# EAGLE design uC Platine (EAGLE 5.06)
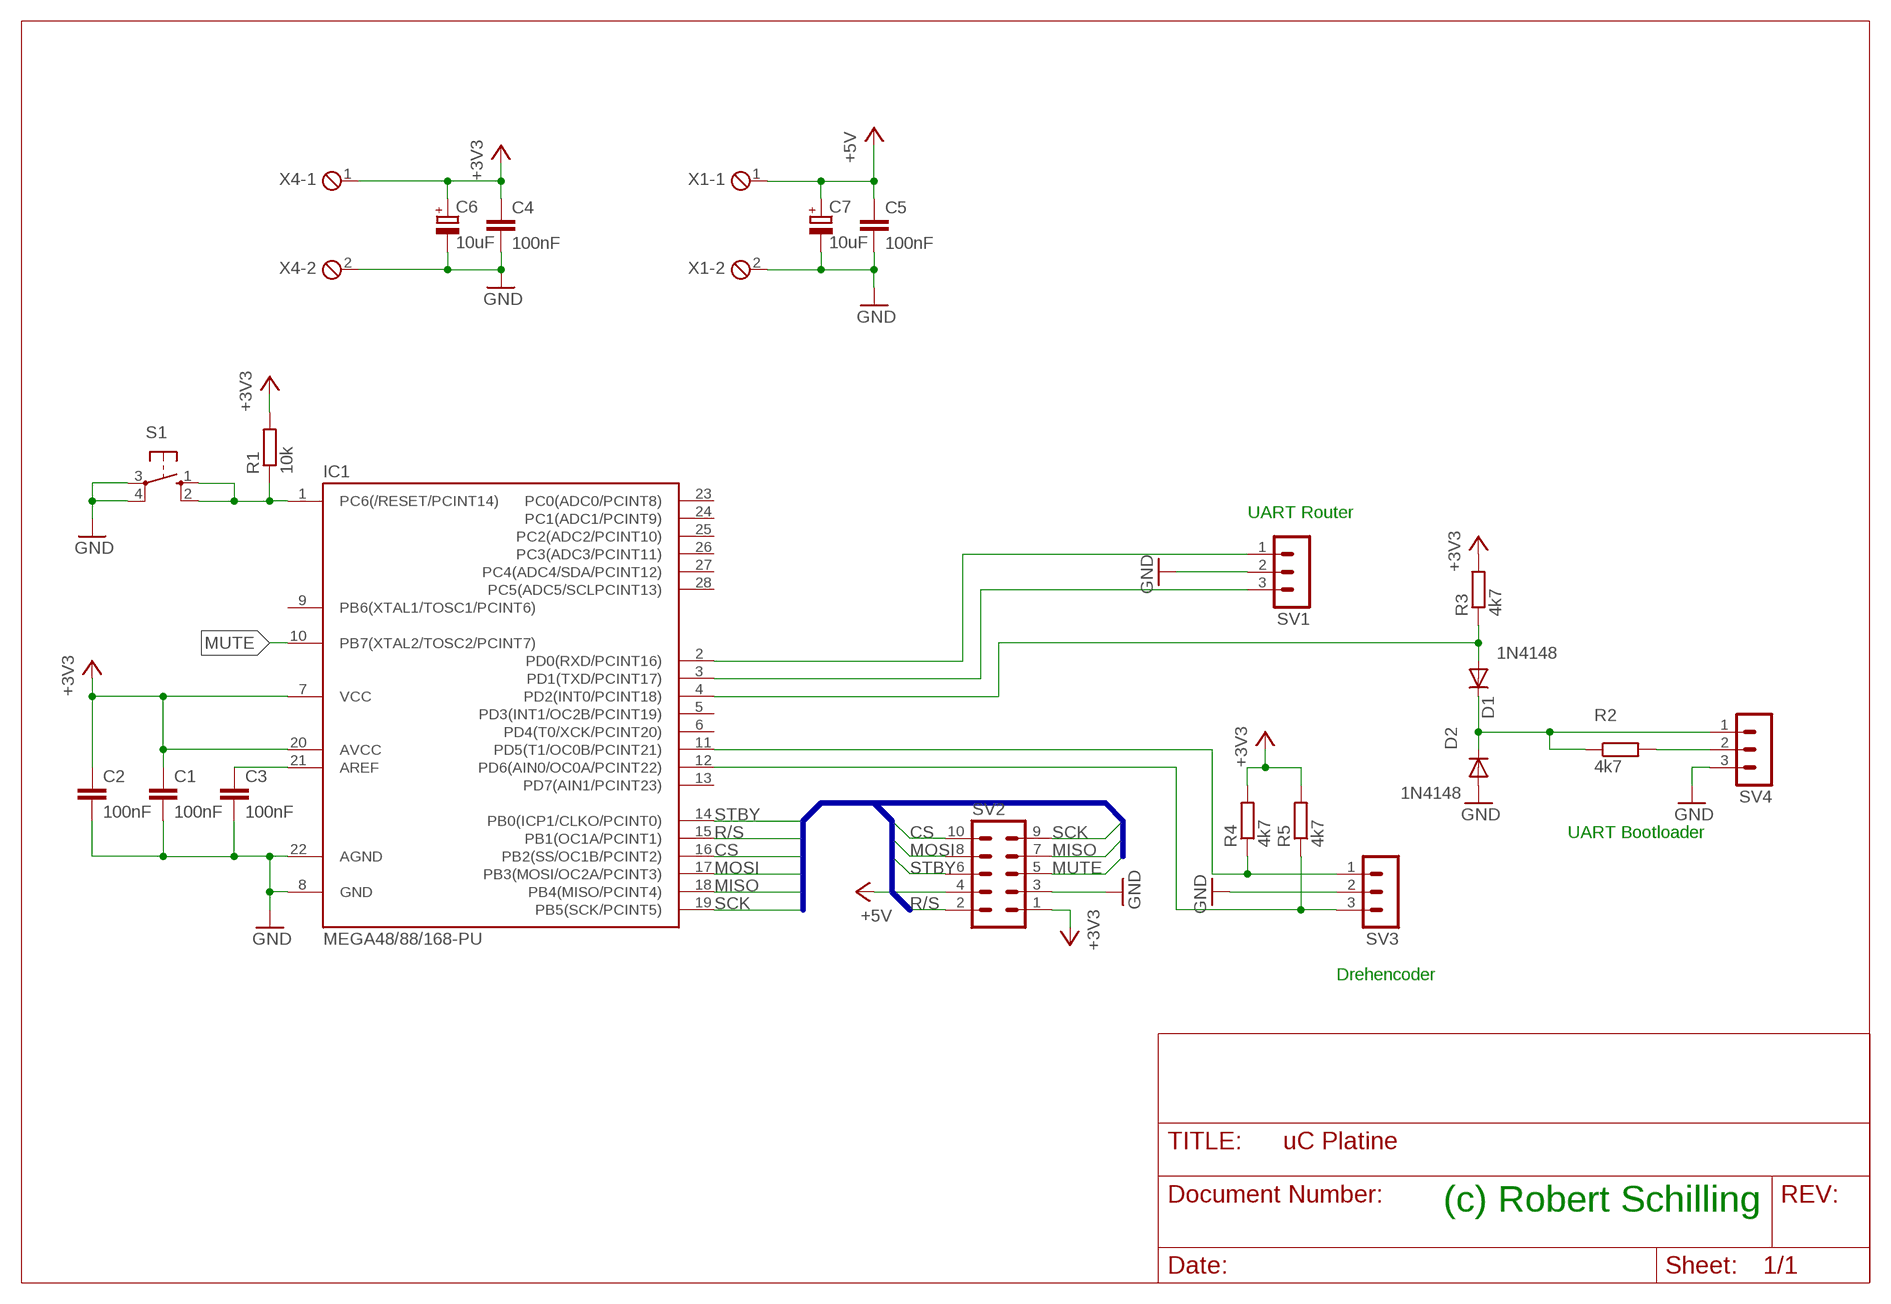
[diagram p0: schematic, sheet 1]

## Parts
C1  100nF  C-EUC0805  [C0805]
C2  100nF  C-EUC0805  [C0805]
C3  100nF  C-EUC0805  [C0805]
C4  100nF  C-EUC0805  [C0805]
C5  100nF  C-EUC0805  [C0805]
C6  10uF  CPOL-EUE2.5-6  [E2,5-6]
C7  10uF  CPOL-EUE2.5-6  [E2,5-6]
D1  1N4148  DIODE-MINIMELF  [MINIMELF]
D2  1N4148  DIODE-MINIMELF  [MINIMELF]
IC1  MEGA48/88/168-PU  [DIL28-3]
R1  10k  R-EU_M0805  [M0805]
R2  4k7  R-EU_M0805  [M0805]
R3  4k7  R-EU_M0805  [M0805]
R4  4k7  R-EU_M0805  [M0805]
R5  4k7  R-EU_M0805  [M0805]
S1  10-XX  [B3F-10XX]
SV1  MA03-1  [MA03-1]
SV2  ML10  [ML10]
SV3  MA03-1  [MA03-1]
SV4  MA03-1  [MA03-1]
X1  MKDS1.5-2  [MKDS1.5-2]
X4  MKDS1.5-2  [MKDS1.5-2]

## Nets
+3V3: C1.1 C2.1 C4.1 C6.+ IC1.7(VCC) IC1.20(AVCC) R1.2 R3.2 R4.2 R5.2 SV2.1 X4.1
+5V: C5.1 C7.+ SV2.4 X1.1
CS: IC1.16(PB2(SS/OC1B/PCINT2)) SV2.10
GND: C1.2 C2.2 C3.2 C4.2 C5.2 C6.- C7.- D2.A IC1.8(GND) IC1.22(AGND) S1.3(P) S1.4(P1) SV1.2 SV2.3 SV3.2 SV4.3 X1.2 X4.2
MISO: IC1.18(PB4(MISO/PCINT4)) SV2.7
MOSI: IC1.17(PB3(MOSI/OC2A/PCINT3)) SV2.8
MUTE: IC1.10(PB7(XTAL2/TOSC2/PCINT7)) SV2.5
N$1: IC1.2(PD0(RXD/PCINT16)) SV1.1
N$2: C3.1 IC1.21(AREF)
N$3: D1.C D2.C R2.1 SV4.1
N$4: R2.2 SV4.2
N$5: IC1.1(PC6(/RESET/PCINT14)) R1.1 S1.1(S) S1.2(S1)
N$6: IC1.3(PD1(TXD/PCINT17)) SV1.3
N$7: D1.A IC1.4(PD2(INT0/PCINT18)) R3.1
N$9: IC1.11(PD5(T1/OC0B/PCINT21)) R4.1 SV3.1
N$10: IC1.12(PD6(AIN0/OC0A/PCINT22)) R5.1 SV3.3
R/S: IC1.15(PB1(OC1A/PCINT1)) SV2.2
SCK: IC1.19(PB5(SCK/PCINT5)) SV2.9
STBY: IC1.14(PB0(ICP1/CLKO/PCINT0)) SV2.6
Unconnected: IC1.5(PD3(INT1/OC2B/PCINT19)) IC1.6(PD4(T0/XCK/PCINT20)) IC1.9(PB6(XTAL1/TOSC1/PCINT6)) IC1.13(PD7(AIN1/PCINT23)) IC1.23(PC0(ADC0/PCINT8)) IC1.24(PC1(ADC1/PCINT9)) IC1.25(PC2(ADC2/PCINT10)) IC1.26(PC3(ADC3/PCINT11)) IC1.27(PC4(ADC4/SDA/PCINT12)) IC1.28(PC5(ADC5/SCLPCINT13))

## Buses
B$1

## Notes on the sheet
- UART Router
- UART Bootloader
- Drehencoder
- (c) Robert Schilling

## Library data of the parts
C1-C5 = resistor:C-EU: CAPACITOR, European symbol
C6 C7 = resistor:CPOL-EU: POLARIZED CAPACITOR, European symbol
D1 D2 = diode:DIODE-: DIODE
IC1 = avr-6:MEGA48/88/168-PU
R1-R5 = rcl:R-EU_: RESISTOR, European symbol
S1 = switch-omron:10-XX: OMRON SWITCH
SV1 SV3 SV4 = con-lstb:MA03-1: PIN HEADER
SV2 = con-harting-ml:ML10: HARTING
X1 X4 = HTL-Diplomarbeit_Knapp:MKDS1.5-2

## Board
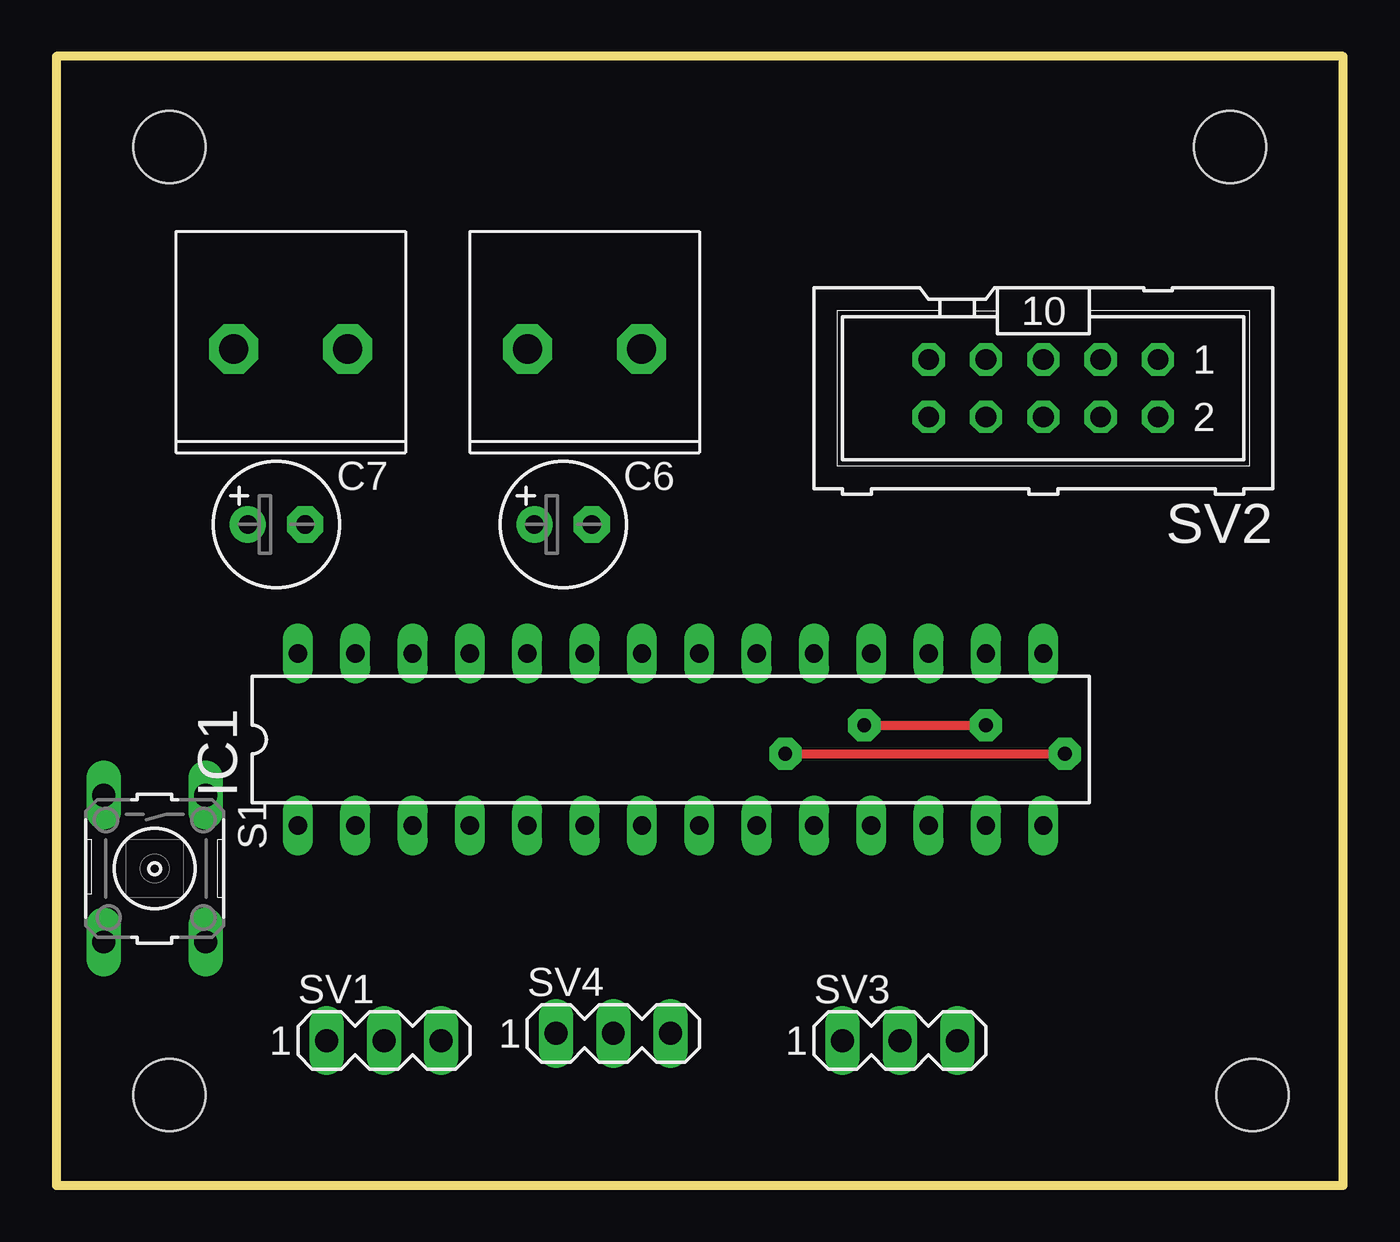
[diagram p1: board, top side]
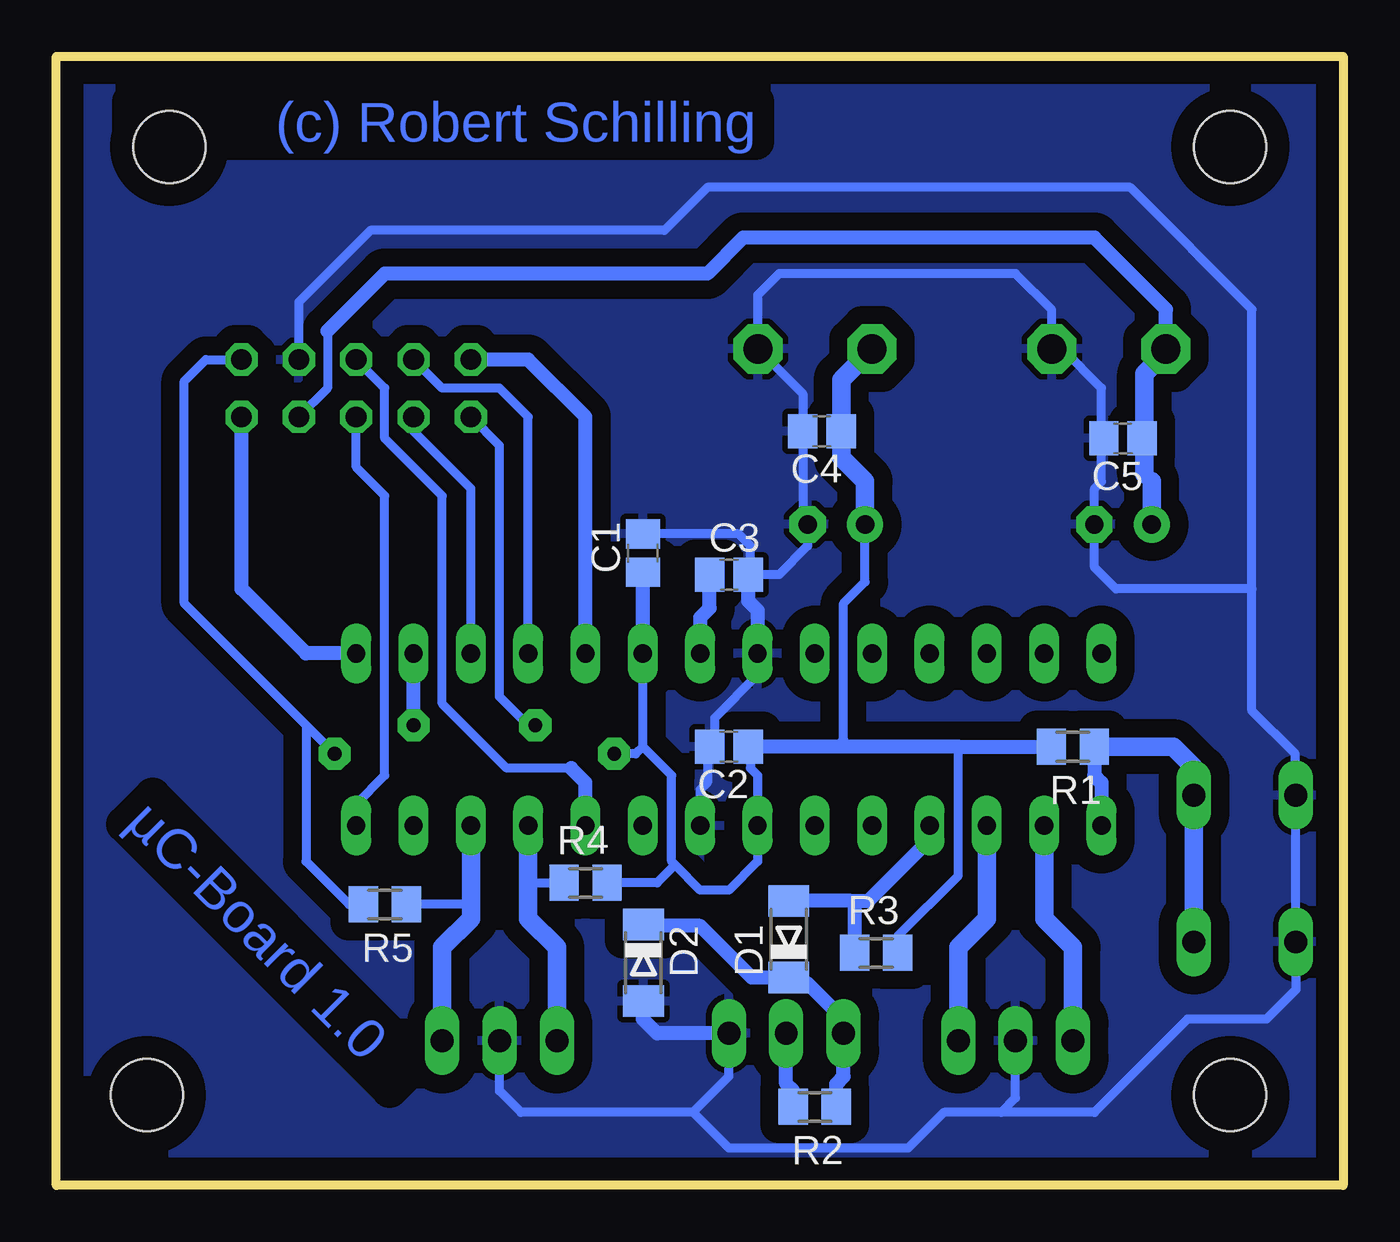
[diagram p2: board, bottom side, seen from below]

Size 57 x 50 mm. Coordinates in mm from the lower left corner, seen from the top.
Outline: 0,0 57,0 57,50 0,50 0,0
Copper layers (1*16): Top 0.035mm / dielectric 1.5mm / Bottom 0.035mm
Design rules "default *": minimum track width 10mil, minimum drill 24mil, track to track 8mil, track to pad 8mil, pad to pad 8mil, via to via 8mil, smd to smd 8mil, copper to edge 40mil, drill to drill 8mil, minimum pad ring 10mil, minimum via ring 8mil, stop-mask expansion 4mil, vias tented up to drill 0mil, thermal gap 10mil
Holes 3.2 mm at 52,46 53,4 5,4 5,46

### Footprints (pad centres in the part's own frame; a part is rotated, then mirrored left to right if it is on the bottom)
C0805 = smd 1.3 x 1.5: 1 -0.85,0; 2 0.85,0
E2,5-6 = drill 0.813 pad 1.6 round: + -1.27,0 | drill 0.813 pad 1.6 octagon: - 1.27,0
MINIMELF = smd 1.4 x 1.8: A 1.7,0; C -1.7,0
DIL28-3 = drill 0.813 long: 1 -16.51,-3.81; 2 -13.97,-3.81; 3 -11.43,-3.81; 4 -8.89,-3.81; 5 -6.35,-3.81; 6 -3.81,-3.81; 7 -1.27,-3.81; 8 1.27,-3.81; 9 3.81,-3.81; 10 6.35,-3.81; 11 8.89,-3.81; 12 11.43,-3.81; 13 13.97,-3.81; 14 16.51,-3.81; 15 16.51,3.81; 16 13.97,3.81; 17 11.43,3.81; 18 8.89,3.81; 19 6.35,3.81; 20 3.81,3.81; 21 1.27,3.81; 22 -1.27,3.81; 23 -3.81,3.81; 24 -6.35,3.81; 25 -8.89,3.81; 26 -11.43,3.81; 27 -13.97,3.81; 28 -16.51,3.81
M0805 = smd 1.3 x 1.6: 1 -0.95,0; 2 0.95,0
B3F-10XX = drill 1.016 long: 1 -3.251,2.261; 2 3.251,2.261; 3 -3.251,-2.261; 4 3.251,-2.261
MA03-1 = drill 1.016 long: 1 -2.54,0; 2 0,0; 3 2.54,0
ML10 = drill 0.914 octagon: 1 -5.08,-1.27; 2 -5.08,1.27; 3 -2.54,-1.27; 4 -2.54,1.27; 5 0,-1.27; 6 0,1.27; 7 2.54,-1.27; 8 2.54,1.27; 9 5.08,-1.27; 10 5.08,1.27
MKDS1.5-2 = drill 1.3 pad 2.184 octagon: 1 2.55,4.6; 2 7.6,4.6

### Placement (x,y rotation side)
C1  31.02,28.01 90 bottom
C2  27.21,19.43 180 bottom
C3  27.21,27.05 0 bottom
C4  23.08,33.4 180 bottom
C5  9.75,33.09 180 bottom
C6  22.45,29.27 0 top
C7  9.75,29.27 0 top
D1  24.55,10.91 90 bottom
D2  30.99,9.86 270 bottom
IC1  27.21,19.75 0 top
R1  11.97,19.43 180 bottom
R2  23.4,3.48 180 bottom
R3  20.68,10.3 0 bottom
R4  33.56,13.4 0 bottom
R5  42.45,12.45 180 bottom
S1  4.35,14.04 270 top
SV1  14.51,6.41 0 top
SV2  43.72,35.31 180 top
SV3  37.37,6.41 0 top
SV4  24.67,6.73 0 top
X1  5.3,32.45 0 top
X4  18.32,32.45 0 top

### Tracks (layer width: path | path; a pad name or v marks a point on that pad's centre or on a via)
+3V3  (via drill 0.61 pad 1.42)
  Top 0.406: v32.29,19.11 v44.67,19.11
  Bottom 0.406: C2.1 26.26,19.33 26.26,18.48 25.94,18.16 IC1.7 25.94,14.35 27.21,13.08 28.48,13.08 29.59,14.19 | C6.+ 21.18,26.73 22.13,25.78 22.13,19.75 22.45,19.43 | R3.2 19.73,11.04 17.05,13.72 17.05,19.43 | 31.02,19.43 IC1.20 | 31.02,19.43 29.75,18.16 29.75,14.35 29.59,14.19 | SV2.1 50.39,36.58 51.34,35.62 51.34,25.78 45.94,20.38 | v44.67,19.11 45.94,20.38 | v32.29,19.11 31.34,19.11 31.02,19.43 | R4.2 30.38,13.4 29.59,14.19 | R5.2 44.04,12.45 45.94,14.35 45.94,20.38
  Bottom 0.61: IC1.20 C1.1 | R1.2 17.05,19.43 22.45,19.43 C2.1
  Bottom 0.813: X4.1 22.23,35.69 C4.1 22.23,32.23 21.18,31.18 C6.+
+5V
  Bottom 0.406: 7.85,36.88 X1.1 | 8.79,33.19 C5.1 8.79,32.98 | SV2.4 44.99,35.31 44.99,37.85
  Bottom 0.61: 8.48,31.18 8.79,31.5 | 44.99,37.85 42.45,40.39 28.16,40.39 26.57,41.98 11.02,41.98 7.84,38.8 X1.1
  Bottom 0.813: 7.85,36.88 8.79,35.94 8.79,33.19 | C7.+ 8.48,31.18 | 8.79,31.5 8.79,32.98
CS  (via drill 0.61 pad 1.42)
  Top 0.406: v35.78,20.38 v41.18,20.38
  Bottom 0.406: SV2.10 37.37,32.77 37.37,21.66 36.1,20.38 v35.78,20.38
  Bottom 0.61: v41.18,20.38 IC1.16
GND
  Bottom 0.406: C1.2 26.79,28.85 26.26,28.32 26.26,27.16 C3.2 24.99,27.05 23.72,28.32 C6.- 23.93,29.49 C4.2 23.93,35.06 X4.2 25.94,37.07 25.94,39.44 24.99,40.39 14.51,40.39 12.9,38.78 X1.2 12.44,37.05 10.7,35.31 10.7,33.19 C5.2 10.7,32.98 10.7,31.18 11.02,30.86 C7.- 11.02,27.37 10.06,26.42 4.03,26.42 | IC1.8 28.48,17.53 28.16,17.84 28.16,19.33 C2.2 27.84,19.65 27.84,20.7 25.94,22.61 IC1.22 | SV1.2 14.51,3.88 15.14,3.24 | SV3.2 37.37,4.19 36.42,3.24 28.8,3.24 | SV2.3 46.26,39.12 43.09,42.29 30.07,42.29 28.16,44.2 9.43,44.2 4.03,38.8 4.03,26.42 | 31.02,7.37 31.02,8.14 D2.A | 28.8,3.24 27.21,4.83 SV4.3 | 15.14,3.24 17.68,3.24 19.27,1.65 27.21,1.65 28.8,3.24 | 15.14,3.24 11.02,3.24 6.89,7.37 3.4,7.37 2.09,8.68 S1.4 S1.3 2.13,17.32 2.13,19.11 4.03,21.02 4.03,26.42
  Bottom 0.61: C3.2 26.36,25.88 25.94,25.47 IC1.22 | SV4.3 30.38,6.73 31.02,7.37
  pour Bottom (isolate 0.813): 0,0 57,0 57,50 0,50
MISO
  Bottom 0.406: IC1.18 36.1,34.04 37.37,35.31 39.91,35.31 SV2.7
MOSI
  Bottom 0.406: IC1.17 38.64,30.86 41.18,33.4 SV2.8
MUTE
  Bottom 0.406: SV2.5 42.45,35.31 42.45,33.09 39.91,30.55 39.91,21.34 37.05,18.48 34.2,18.48
  Bottom 0.61: IC1.10 33.56,17.84 34.2,18.48
N$1
  Bottom 0.813: IC1.2 13.24,11.81 11.97,10.54 SV1.1
N$2
  Bottom 0.61: C3.1 28.06,25.57 28.48,25.15 IC1.21
N$3
  Bottom 0.406: SV4.1 22.13,7.37 | 24.3,8.95 D1.C | 30.92,11.5 D2.C
  Bottom 0.61: R2.1 22.45,4.5 22.13,4.83 SV4.1 | 22.13,7.37 23.72,8.95 24.3,8.95 | D1.C 26.19,9.2 28.48,11.5 30.92,11.5
N$4
  Bottom 0.406: R2.2 24.35,4.19
  Bottom 0.61: 24.35,4.19 24.67,4.51 SV4.2
N$5
  Bottom 0.61: R1.1 11.02,18.16 10.7,17.84 IC1.1
  Bottom 0.813: S1.2 S1.1 6.61,18.52 7.53,19.43 R1.1
N$6
  Bottom 0.813: IC1.3 15.78,11.81 17.05,10.54 SV1.3
N$7
  Bottom 0.406: 18.32,15.3 IC1.4 | 21.63,12.43 21.81,12.61
  Bottom 0.61: D1.A 21.81,12.61 21.02,12.61 18.32,15.3 | R3.1 21.63,12.43
N$9
  Bottom 0.406: 36.1,13.4 R4.1
  Bottom 0.813: IC1.11 36.1,13.4 36.1,11.81 34.83,10.54 SV3.1
N$10
  Bottom 0.406: R5.1 38.96,12.45 38.64,12.77
  Bottom 0.813: IC1.12 38.64,12.77 38.64,11.81 39.91,10.54 SV3.3
R/S
  Bottom 0.61: SV2.2 48.8,26.42 45.94,23.56 IC1.15
SCK
  Bottom 0.61: IC1.19 33.56,34.04 36.1,36.58 SV2.9
STBY
  Bottom 0.406: SV2.6 43.72,31.81 42.45,30.55 42.45,18.16 43.72,16.89 IC1.14

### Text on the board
Bottom: (c) Robert Schilling | µC-Board 1.0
